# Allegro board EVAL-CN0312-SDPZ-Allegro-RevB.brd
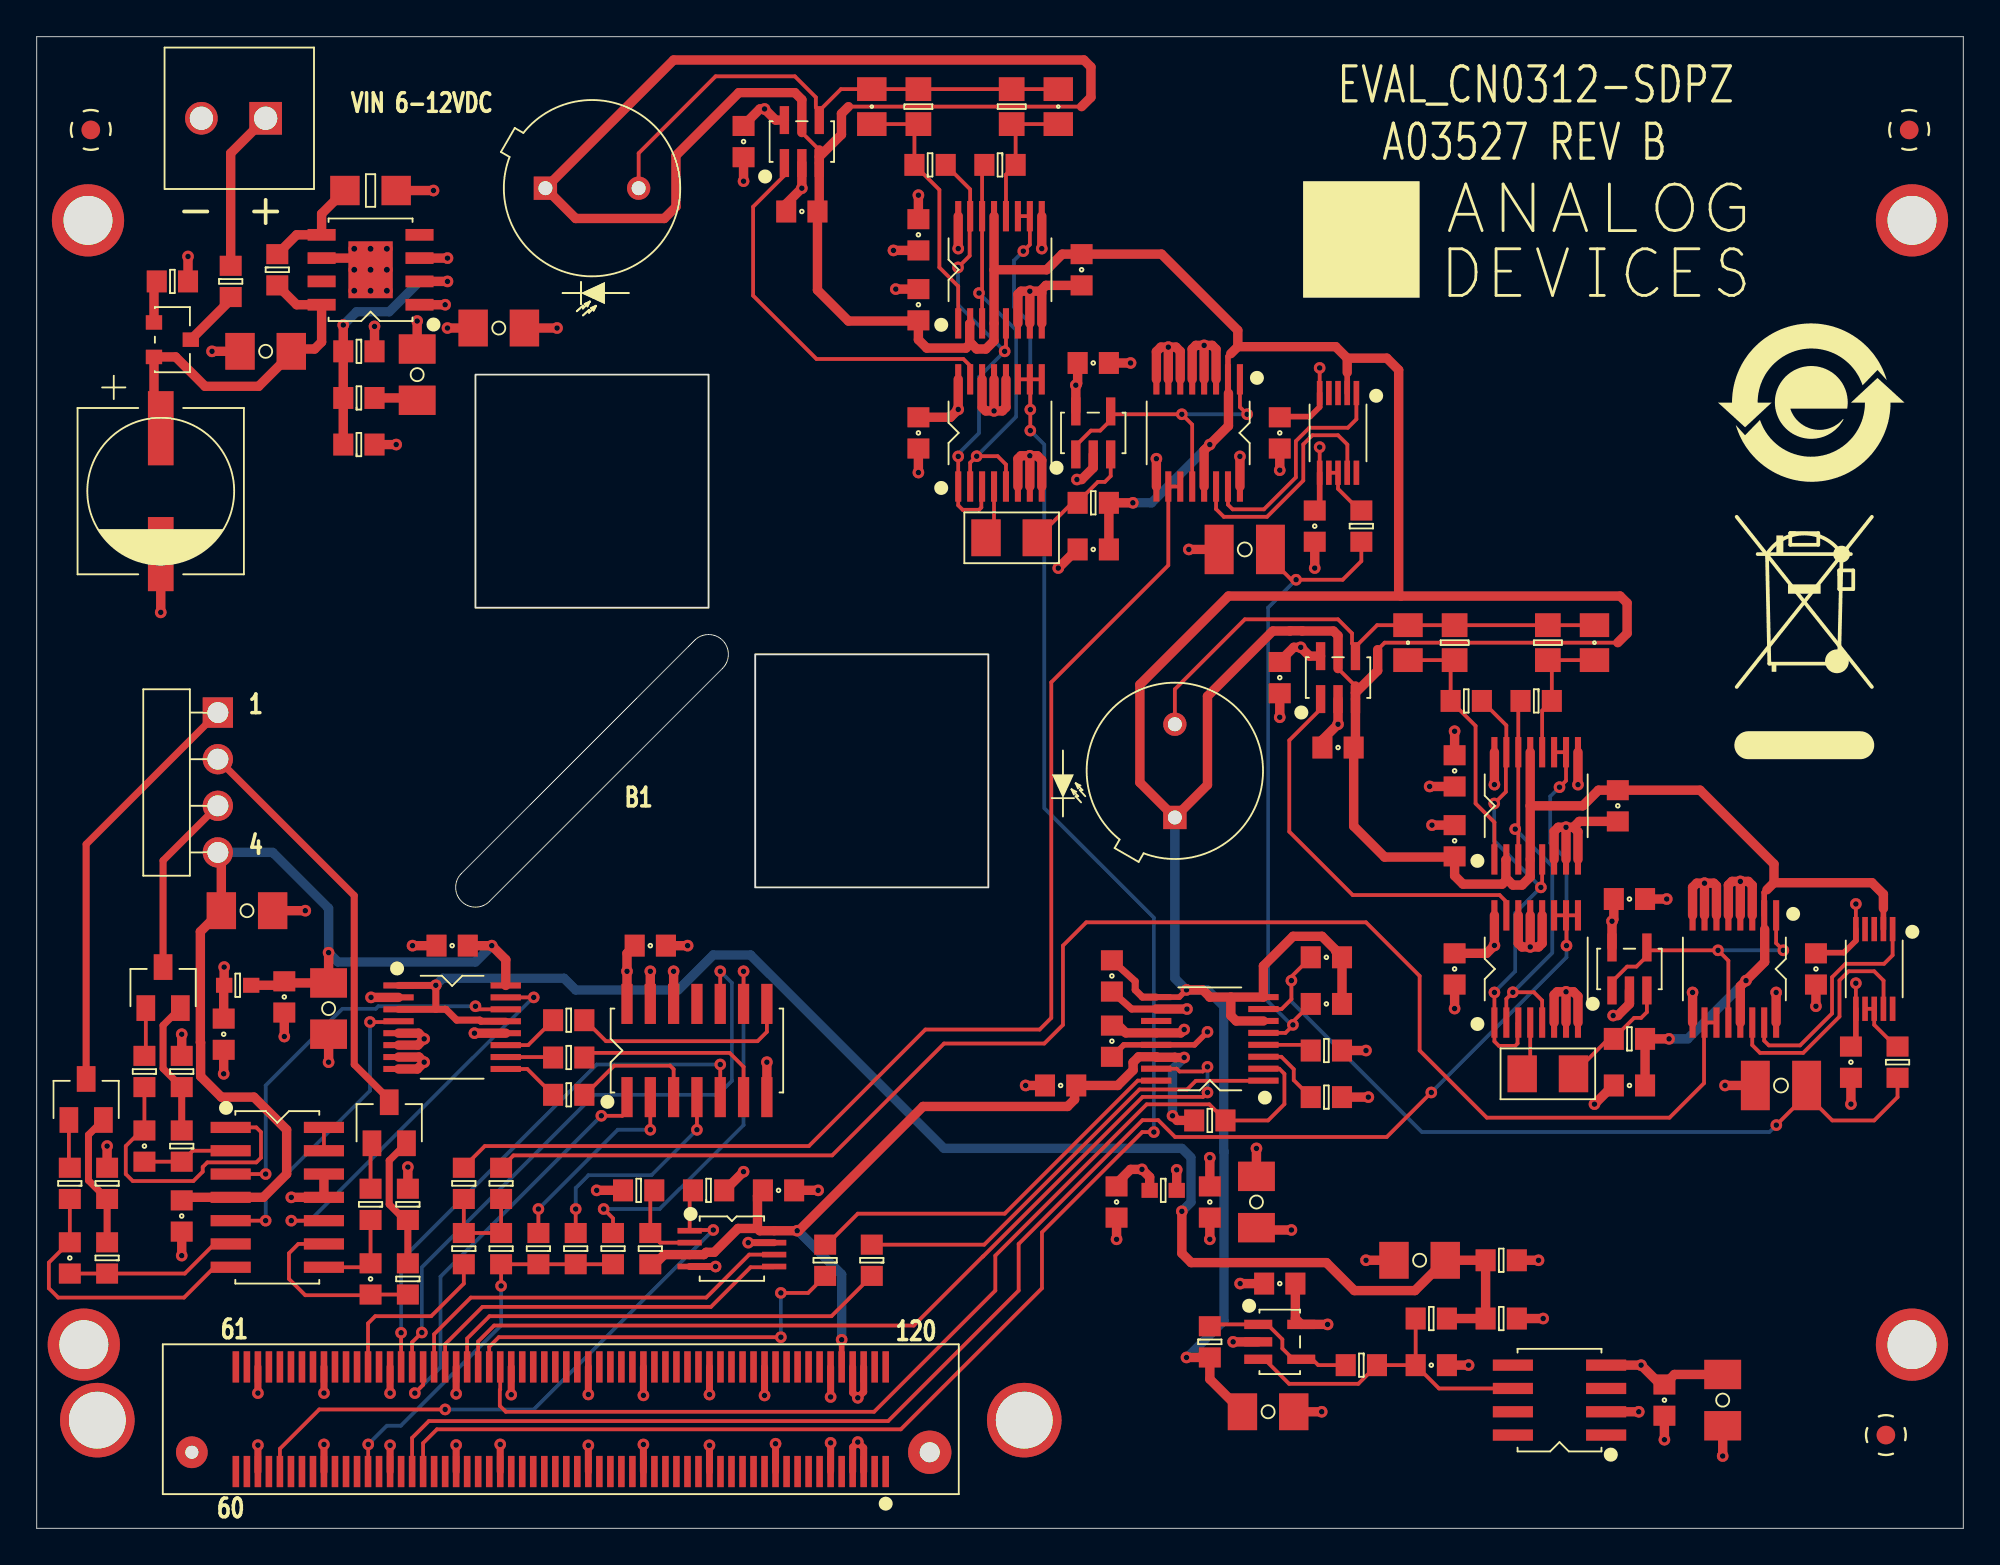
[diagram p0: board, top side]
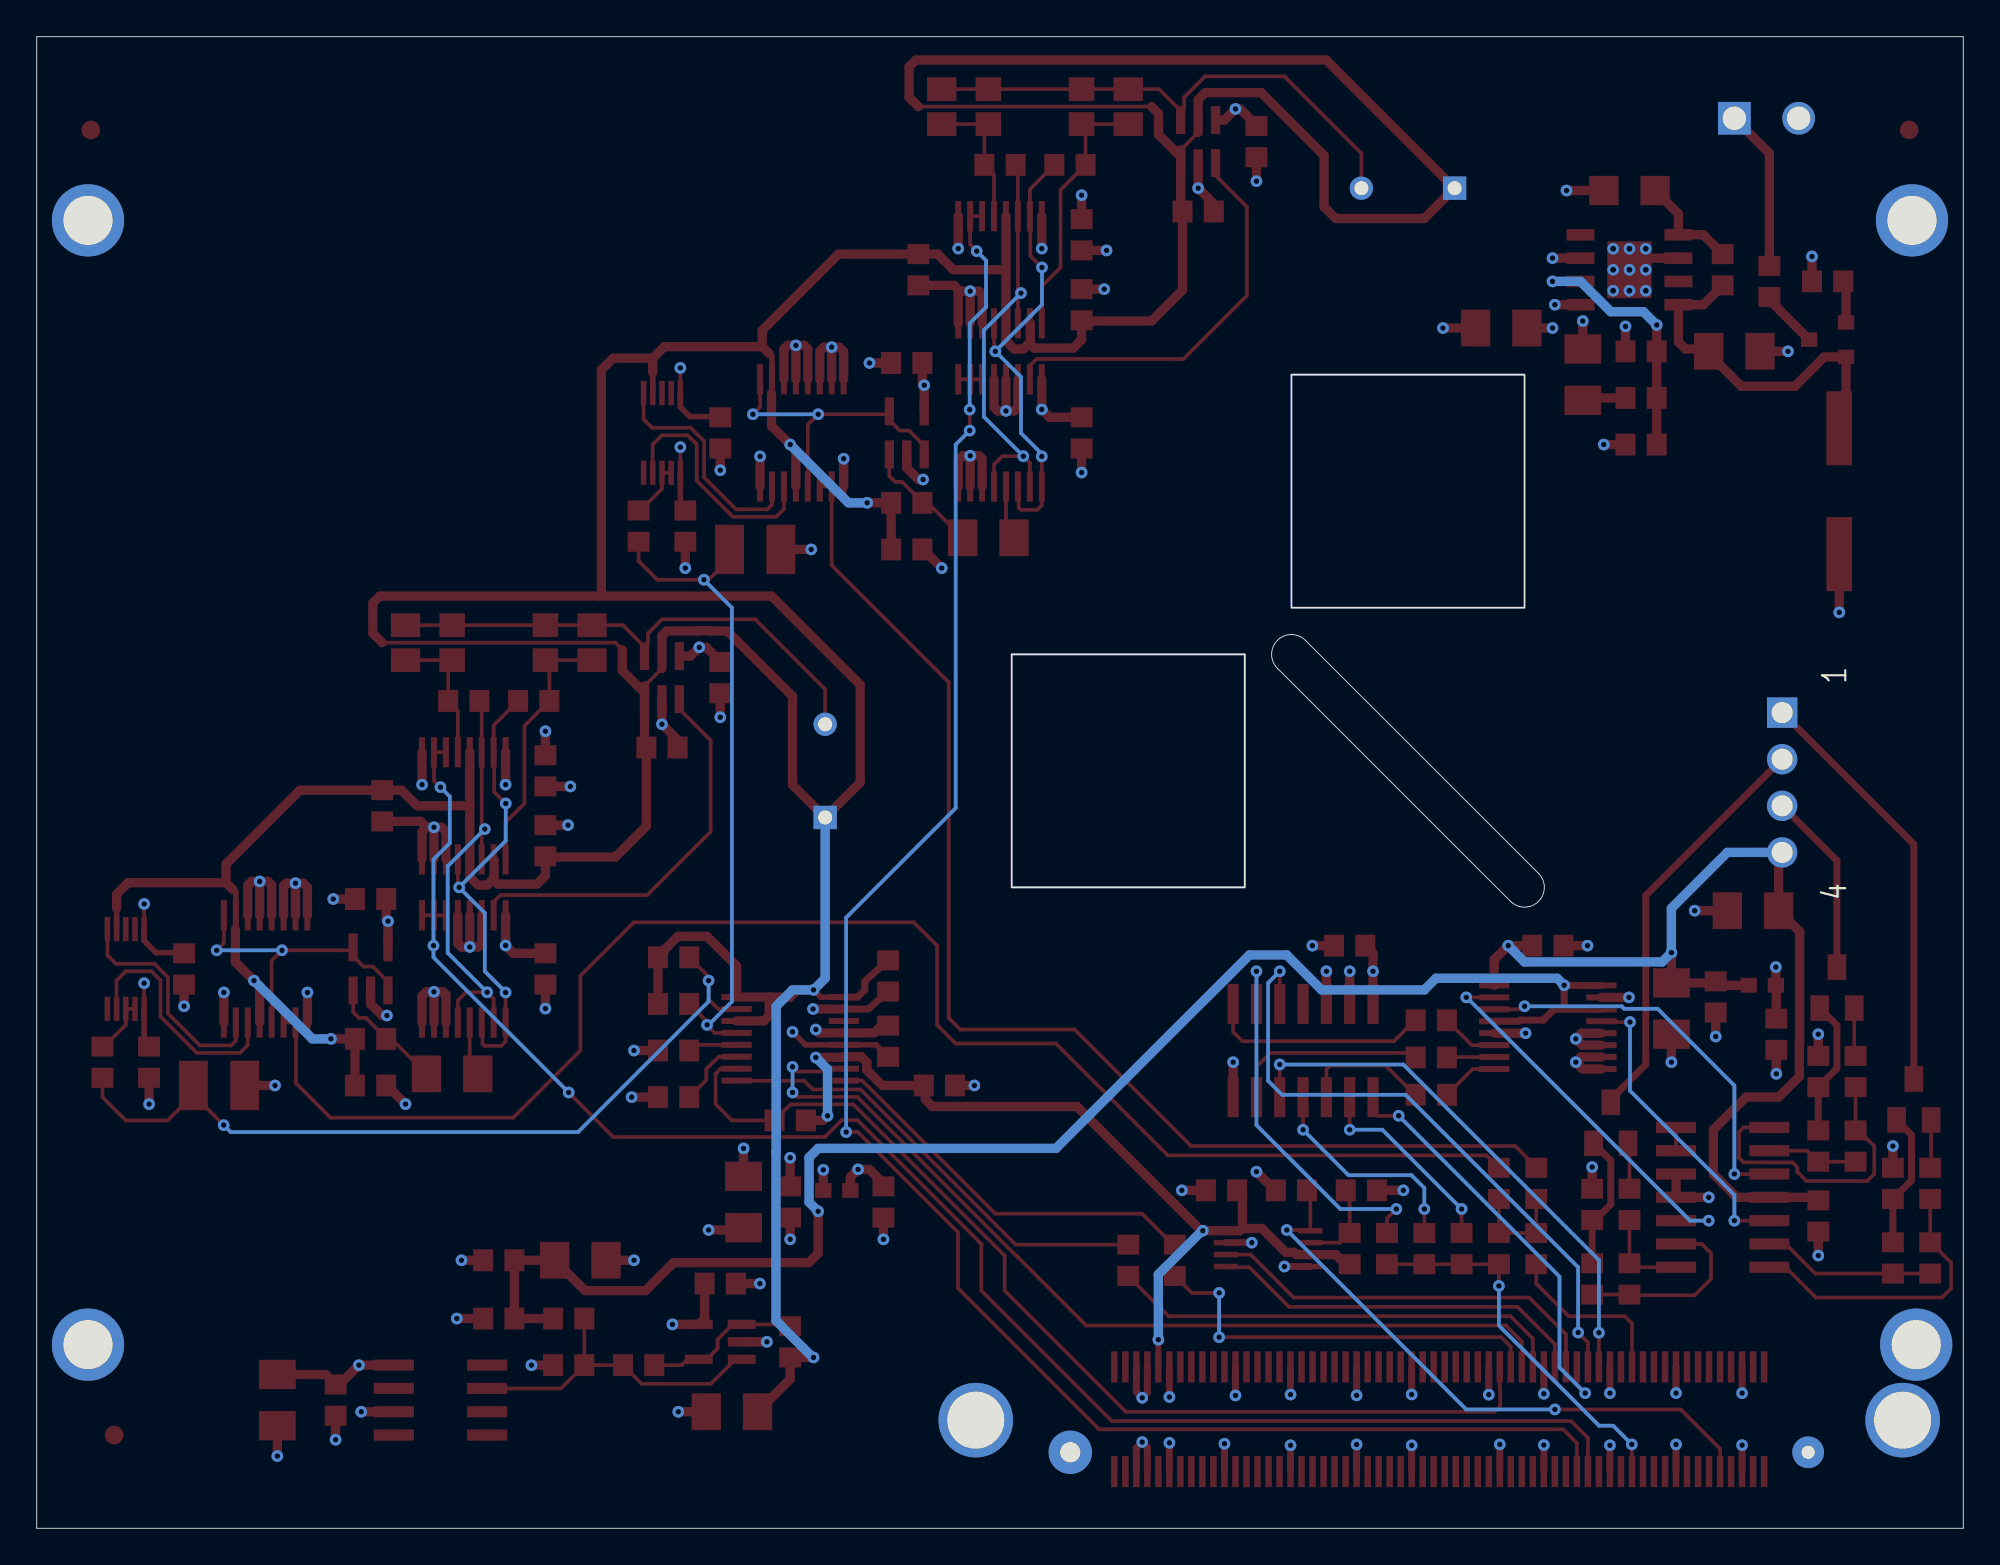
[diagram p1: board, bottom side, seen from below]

Outline 104.95 x 81.28 mm; copper layers: TOP, L2_GND, L3_PWR, BOTTOM. Coordinates in mm from the lower left corner of the outline.
Outline path: rectangle 23.9,50.16 36.6,62.87 ; rectangle 39.14,34.92 51.84,47.62 ; 0,81.28 0,0 104.95,0 104.95,81.28 0,81.28 ; 24.66,34.16 arc(23.14,34.16) 23.14,35.69 35.84,48.39 arc(37.36,48.39) 37.36,46.86 24.66,34.16

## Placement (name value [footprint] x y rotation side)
C1  0.1uF  [C0603]  58.57 30.1 270 top
C2  0.1uF  [C0603]  70.26 28.58 0 top
C3  0.1uF  [C0603]  58.83 17.78 270 top
C4  0.1uF  [C0603]  63.91 17.78 270 top
C5  2.2uF  [C1206]  75.34 14.61 180 top
C6  2.2uF  [C1206]  67.08 6.35 0 top
C7  0.1uF  [C0603]  48.03 66.67 90 top
C8  0.1uF  [C0603]  41.68 71.75 180 top
C9  0.1uF  [C0603]  57.56 53.34 180 top
C10  0.1uF  [C0603]  56.92 68.58 270 top
C11  0.22uF  [C1206H37]  82.32 24.77 0 top
C12  2.2uF  [C1206]  11.46 33.66 0 top
C13  0.1uF  [C0603]  22.63 31.75 180 top
C14  TBD0603  [C0603]  5.87 20.83 90 top
C15  0.1uF  [C0603]  67.72 46.36 270 top
C16  2.2uF  [C1206]  15.9 28.32 270 top
C17  0.1uF  [C0603]  77.24 41.27 270 top
C18  0.1uF  [C0603]  77.24 30.48 270 top
C19  0.1uF  [C0603]  7.9 17.02 270 top
C20  0.1uF  [C0603]  88.67 6.98 90 top
C21  0.1uF  [C0603]  13.49 28.96 270 top
C22  0.1uF  [C0603]  67.72 13.34 180 top
C23  2.2uF  [C1206]  91.85 6.98 90 top
C24  0.22uF  [C1206H37]  53.11 53.98 0 top
C25  2.2uF  [C1206]  66.45 17.78 270 top
C26  4.7pF  [C0805]  45.49 77.47 270 top
C27  0.1uF  [C0603]  38.51 75.56 270 top
C28  0.1uF  [C0603]  55.78 24.13 180 top
C29  15pF  [C0805]  55.65 77.47 270 top
C30  0.1uF  [C0603]  48.03 70.48 270 top
C31  0.1uF  [C0603]  48.03 59.69 270 top
C32  0.1uF  [C0603]  86.77 34.29 0 top
C33  0.1uF  [C0603]  70.89 42.55 180 top
C34  0.1uF  [C0603]  86.77 24.13 180 top
C35  0.1uF  [C0603]  77.24 37.47 90 top
C36  0.1uF  [C0603]  86.13 39.37 270 top
C37  0.1uF  [C0603]  96.93 30.48 90 top
C38  0.1uF  [C0603]  57.56 63.5 0 top
C39  0.1uF  [C0603]  98.83 25.4 270 top
C40  0.1uF  [C0603]  67.72 59.69 90 top
C41  0.1uF  [C0603]  69.62 54.61 270 top
C42  1uF  [C1210]  65.81 53.34 180 top
C43  0.1uF  [C0603]  58.57 26.54 90 top
C44  1uF  [C1210]  95.02 24.13 180 top
C45  0.1uF  [C0603]  75.97 8.89 0 top
C46  0.1uF  [C0603]  70.26 31.12 0 top
C47  0.1uF  [C0603]  40.41 18.41 0 top
C48  TBD0603  [C0603]  1.8 14.73 90 top
C49  0.1uF  [C0603]  33.43 31.75 0 top
C51  100uF  [CPLSML327W327H413]  6.76 56.52 270 top
C52  2.2uF  [C1206]  12.47 64.14 180 top
C53  4.7pF  [C0805]  74.7 48.26 270 top
C54  2.2uF  [C1206]  25.17 65.41 0 top
C55  0.02uF  [C1206]  20.73 62.87 270 top
C56  15pF  [C0805]  84.86 48.26 270 top
C57  0.1uF  [C0603]  10.19 26.92 270 top
C58  TBD0603  [C0603]  18.19 13.59 90 top
D2  S1336-44BK  [TO5_A]  30.25 73.03 0 top
D3  S1336-44BK  [TO5_A]  62 41.27 90 top
J1  TSW-104-09-G-S-RA  [CNSAMTECTSW-104-09-G-S-RA]  6.76 40.64 270 top
J2  25.195.0253.0  [CNWIELAND0253]  12.47 76.84 180 top
J4  FX8-120S-SV(21)  [CNHRSFX8-120S-SV]  28.55 5.94 180 top
L1  330OHM  [L0603]  61.37 18.41 180 top
L2  330OHM  [L0603]  10.95 29.59 180 top
NOREF  -  []  104.95 0 90 top
NOREF#2  -  [unnamed#2]  102.16 71.27 0 top
NOREF#3  -  []  161.7 251.46 0 top
NOREF#4  -  []  0 81.28 0 top
NOREF#5  -  []  96.67 61.34 0 top
NOREF#6  -  [unnamed#2]  2.95 76.2 0 top
NOREF#7  -  []  30.25 67.31 180 top
NOREF#8  -  []  3.3 4.62 0 top
NOREF#9  -  []  39.14 46.36 0 top
NOREF#10  -  []  0 81.28 270 top
NOREF#11  -  []  3.3 5.89 0 top
NOREF#12  -  []  30.25 67.31 180 top
NOREF#13  -  [unnamed#2]  102.01 76.2 0 top
NOREF#14  -  []  -191.36 -58.42 0 top
NOREF#15  -  []  23.9 34.92 90 top
NOREF#16  -  []  53.8 5.89 90 top
NOREF#17  -  []  52.53 5.89 90 top
NOREF#18  -  [unnamed#2]  53.8 5.89 0 top
NOREF#19  -  []  0 0 0 top
NOREF#20  -  []  -115.16 -124.46 0 top
NOREF#21  -  [unnamed#2]  3.3 5.89 0 top
NOREF#22  -  []  55.91 40.39 270 top
NOREF#23  -  []  190.91 -1.27 0 top
NOREF#24  -  []  -256.77 -241.94 0 top
NOREF#25  -  [unnamed#2]  100.74 5.08 0 top
NOREF#26  -  []  0 0 90 top
NOREF#27  -  []  105.56 58.8 0 top
NOREF#28  -  []  -214.22 213.36 0 top
NOREF#29  -  []  0 0 0 top
NOREF#30  -  []  0 0 0 top
NOREF#31  -  []  35.33 50.16 90 top
NOREF#32  -  []  104.95 81.28 180 top
NOREF#33  -  []  23.42 33.96 0 top
NOREF#34  -  []  23.9 34.92 0 top
NOREF#35  -  []  0 0 90 top
NOREF#36  -  [unnamed#2]  2.79 71.27 0 top
NOREF#37  -  [unnamed#2]  2.57 10.01 0 top
NOREF#38  -  []  104.95 0 90 top
NOREF#39  -  [unnamed#2]  102.16 10.01 0 top
NOREF#40  -  []  54.38 93.98 0 top
NOREF#41  -  []  68.99 67.06 180 bottom
Q1  MMBT4401  [SOT23]  6.88 29.46 0 top
Q2  MMBT4401  [SOT23]  2.69 23.37 0 top
Q3  MMBT4401  [SOT23]  19.2 22.1 0 top
Q4  SI2301CDS-T1-E3  [SOT23-M3]  7.39 64.77 270 top
R1  10K  [R0603]  57.56 55.88 0 top
R2  1MEG  [R0805]  48.03 77.47 270 top
R3  33  [R0603]  5.87 24.89 90 top
R4  10K  [R0603]  75.97 11.43 0 top
R5  10K  [R0603]  79.78 11.43 0 top
R6  TBD0603  [R0603]  52.48 74.3 180 top
R7  TBD0603  [R0603]  48.67 74.3 0 top
R8  10K  [R0603]  86.77 26.67 0 top
R9  10K  [R0603]  72.16 54.61 270 top
R10  10K  [R0603]  101.37 25.4 270 top
R11  TBD0603  [R0603]  77.88 45.09 0 top
R12  100  [R0603]  7.9 24.89 90 top
R13  33  [R0603]  7.9 20.83 90 top
R14  1MEG  [R0805]  77.24 48.26 270 top
R15  0  [R0603]  72.16 8.89 180 top
R16  10K  [R0603]  70.26 26.04 0 top
R17  10K  [R0603]  70.26 23.5 0 top
R18  100  [R0603]  3.84 18.8 90 top
R19  33  [R0603]  1.8 18.8 90 top
R20  10K  [R0603]  79.78 14.61 0 top
R21  33K  [R0805]  53.11 77.47 270 top
R22  0  [R0603]  45.49 14.61 90 top
R23  0  [R0603]  42.95 14.61 90 top
R24  33  [R0603]  3.84 14.73 90 top
R25  100  [R0603]  20.22 17.65 90 top
R26  33  [R0603]  18.19 17.65 90 top
R27  TBD0603  [R0603]  81.69 45.09 180 top
R28  0  [R0603]  63.91 10.16 270 top
R29  0  [R0603]  27.33 15.24 90 top
R30  33  [R0603]  20.22 13.59 90 top
R31  TBD0603  [R0603]  33.43 15.24 90 top
R32  100K  [R0603]  36.6 18.41 0 top
R33  100K  [R0603]  63.91 22.23 180 top
R34  0  [R0603]  23.27 15.24 90 top
R35  0  [R0603]  29.36 15.24 90 top
R36  0  [R0603]  25.3 15.24 90 top
R37  0  [R0603]  31.39 15.24 90 top
R38  100  [R0603]  7.39 67.94 0 top
R39  0  [R0603]  23.27 18.8 90 top
R40  0  [R0603]  25.3 18.8 90 top
R41  0  [R0603]  28.98 23.62 180 top
R42  0  [R0603]  28.98 25.65 180 top
R43  0  [R0603]  28.98 27.69 180 top
R44  0  [R0603]  10.57 67.94 270 top
R46  100K  [R0603]  32.79 18.41 180 top
R48  100K  [R0603]  13.11 68.58 270 top
R49  28K  [R1206]  18.19 72.9 0 top
R50  47K  [R0603]  17.55 59.05 0 top
R51  47K  [R0603]  17.55 61.59 0 top
R52  154K  [R0603]  17.55 64.14 180 top
R54  33K  [R0805]  82.32 48.26 270 top
U1  ADG633YRUZ  [TSSOP16]  81.69 30.48 0 top
U2  ADG633YRUZ  [TSSOP16]  81.69 39.37 0 top
U3  AD8615AUJZ  [TSOT-5]  86.77 30.48 0 top
U4  ADG633YRUZ  [TSSOP16]  22.63 27.3 270 top
U5  AD8615AUJZ  [TSOT-5]  70.89 46.36 0 top
U6  AD8618ARZ  [SO14]  13.11 18.03 270 top
U7  AD8615AUJZ  [TSOT-5]  41.68 75.56 0 top
U8  24LC32A-I/MS  [MSOP8]  37.87 15.24 270 top
U9  ADG633YRUZ  [TSSOP16]  52.48 59.69 0 top
U10  ADG633YRUZ  [TSSOP16]  52.48 68.58 0 top
U11  ADG733BRUZ  [TSSOP16]  92.48 30.48 180 top
U12  AD8271ARMZ  [RM10]  100.1 30.48 180 top
U13  AD7798BRUZ  [TSSOP16]  63.91 26.67 90 top
U14  AD8615AUJZ  [TSOT-5]  57.56 59.69 0 top
U15  74AHCT08D,118  [SO14]  35.97 26.04 0 top
U16  ADG733BRUZ  [TSSOP16]  63.27 59.69 180 top
U17  AD8271ARMZ  [RM10]  70.89 59.69 180 top
U18  ADR4525BRZ  [SO8]  82.96 6.98 90 top
U19  AD8605ARTZ  [SOT23-5L]  67.72 10.16 270 top
U20  ADP7104ARDZ  [SO8NB-PAD3_1X2_41]  18.19 68.58 90 top

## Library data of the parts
C1-C4 C7-C10 C13 C15 C17-C22 C27 C28 C30-C41 C43 C45-C47 C49 C57 = CAP: Tolerance: 10; User Part Number: UPN; alternate symbols: (C0402H22_ALT,C0201-2); part number: CAP_SM-0.1UF,100V,10,E013624,C0603; tolerance: 10
C5 C6 C12 C16 C23 C25 C52 C54 = CAP: Tolerance: 10; User Part Number: UPN; alternate symbols: (C0402H22_ALT,C0201-2); part number: CAP_SM-2.2UF,16V,10,E012605,C1206; tolerance: 10
C11 C24 = CAP: Tolerance: 20; User Part Number: UPN; alternate symbols: (C0402H22_ALT,C0201-2); part number: CAP_SM-0.22UF,16V,20,E016730,C1206H37; tolerance: 20
C14 C48 C58 = CAP: User Part Number: UPN; alternate symbols: (C0402H22_ALT,C0201-2); part number: CAP_SM-TBD0603,TBD0603,TBD0603,E000382,C0603
C26 C53 = CAP: Tolerance: 0.25pF; User Part Number: UPN; alternate symbols: (C0402H22_ALT,C0201-2); part number: CAP_SM-4.7PF,50V,0.25PF,E014250,C0805; tolerance: 0.25pF
C29 C56 = CAP: Tolerance: 5; User Part Number: UPN; alternate symbols: (C0402H22_ALT,C0201-2); part number: CAP_SM-15PF,50V,5,E012708,C0805; tolerance: 5
C42 C44 = CAP: Tolerance: 10; User Part Number: UPN; alternate symbols: (C0402H22_ALT,C0201-2); part number: CAP_SM-1UF,50V,10,E011765,C1210; tolerance: 10
C51 = CAPP: Tolerance: 20; User Part Number: UPN; part number: CAPP_SM-100UF,25V,20,E016686,CPLSML327W327H413; tolerance: 20
C55 = CAP: Tolerance: 5; User Part Number: UPN; alternate symbols: (C0402H22_ALT,C0201-2); part number: CAP_SM-0.02UF,50V,5,E013532,C1206; tolerance: 5
D2 D3 = DIOPHOTO_V2: User Part Number: UPN; Tolerance: N/A; part number: DIOPHOTO_V2_TH-S1336-44BK,5V,N/A,E018050,TO5_A; tolerance: N/A
J1 = CN4P: User Part Number: UPN; part number: CN4P_TH-TSW-104-09-G-S-RA,E007556,CNSAMTECTSW-104-09-G-S-RA
J2 = CN2P: User Part Number: UPN; part number: CN2P_TH-25.195.0253.0,E016527,CNWIELAND0253
J4 = CN120P_V2: User Part Number: UPN; part number: CN120P_V2_SM-FX8-120S-SV(21),E010527,CNHRSFX8-120S-SV
L1 L2 = FERRITE: Tolerance: 25; User Part Number: UPN; part number: FERRITE_SM-330OHM,25,E016683,L0603; tolerance: 25
Q1-Q3 = TRANMMBT4401: User Part Number: UPN; part number: TRANMMBT4401_SM-MMBT4401,E004667,SOT23
Q4 = TRANSI2301DS: User Part Number: UPN; part number: TRANSI2301DS_SM-SI2301CDS-T1-E3,E016690,SOT23-M3
R1 R4 R5 R8-R10 R16 R17 R20 = RES: Tolerance: 1; User Part Number: UPN; alternate symbols: (RRAD984L1500W75H520LD32); part number: RES_SM-10K,1/16W,1,E007899,R0603; tolerance: 1
R2 R14 = RES: Tolerance: 1; User Part Number: UPN; alternate symbols: (RRAD984L1500W75H520LD32); part number: RES_SM-1MEG,1/8W,1,E003518,R0805; tolerance: 1
R3 R13 R19 R24 R26 R30 = RES: Tolerance: 1; User Part Number: UPN; alternate symbols: (RRAD984L1500W75H520LD32); part number: RES_SM-33,1/16W,1,E004232,R0603; tolerance: 1
R6 R7 R11 R27 R31 = RES: User Part Number: UPN; alternate symbols: (RRAD984L1500W75H520LD32); part number: RES_SM-TBD0603,TBD0603,TBD0603,E004050,R0603
R12 R18 R25 R38 = RES: Tolerance: 0.1; User Part Number: UPN; alternate symbols: (RRAD984L1500W75H520LD32); part number: RES_SM-100,1/10W,0.1,E003963,R0603; tolerance: 0.1
R15 R22 R23 R28 R29 R34-R37 R39-R44 = RES: Tolerance: 1; User Part Number: UPN; alternate symbols: (RRAD984L1500W75H520LD32); part number: RES_SM-0,1/16W,1,E004207,R0603; tolerance: 1
R21 R54 = RES: Tolerance: 1; User Part Number: UPN; alternate symbols: (RRAD984L1500W75H520LD32); part number: RES_SM-33K,1/10W,1,E004180,R0805; tolerance: 1
R32 R33 R46 R48 = RES: Tolerance: 0.5; User Part Number: UPN; alternate symbols: (RRAD984L1500W75H520LD32); part number: RES_SM-100K,1/10W,0.5,E012705,R0603; tolerance: 0.5
R49 = RES: Tolerance: 1; User Part Number: UPN; alternate symbols: (RRAD984L1500W75H520LD32); part number: RES_SM-28K,1/4W,1,E003411,R1206; tolerance: 1
R50 R51 = RES: Tolerance: 1; User Part Number: UPN; alternate symbols: (RRAD984L1500W75H520LD32); part number: RES_SM-47K,1/16W,1,E004240,R0603; tolerance: 1
R52 = RES: Tolerance: 1; User Part Number: UPN; alternate symbols: (RRAD984L1500W75H520LD32); part number: RES_SM-154K,1/10W,1,E013894,R0603; tolerance: 1
U1 U2 U4 U9 U10 = ADG733: User Part Number: UPN; part number: ADG733_SM-ADG633YRUZ,E012053,TSSOP16,N/A
U3 U5 U7 U14 = AD8605: User Part Number: UPN; part number: AD8605_SM-AD8615AUJZ,E016677,TSOT-5,N/A
U6 = AD713N: User Part Number: UPN; part number: AD713N_SM-AD8618ARZ,E016678,SO14,N/A
U8 = IC24FC256: User Part Number: UPN; part number: IC24FC256_SM-24LC32A-I/MS,E014160,MSOP8
U11 U16 = ADG733: User Part Number: UPN; part number: ADG733_SM-ADG733BRUZ,E011902,TSSOP16,N/A
U12 U17 = AD8271: User Part Number: UPN; part number: AD8271_SM-AD8271ARMZ,E016676,RM10,N/A
U13 = AD779X: User Part Number: UPN; part number: AD779X_SM-AD7798BRUZ,E014198,TSSOP16,N/A
U15 = 7408: User Part Number: UPN; part number: 7408_SM-74AHCT08D,118,E016681,SO14
U18 = ADR45XX: User Part Number: UPN; part number: ADR45XX_SM-ADR4525BRZ,E016680,SO8,N/A
U19 = AD8605: User Part Number: UPN; part number: AD8605_SM-AD8605ARTZ,E006651,SOT23-5L,AD8605
U20 = ADP7104: User Part Number: UPN; part number: ADP7104_SM-ADP7104ARDZ,E016787,SO8NB-PAD3_1X2_41,N/A

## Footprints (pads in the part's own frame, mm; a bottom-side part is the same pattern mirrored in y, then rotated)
C0603
  rect 1.092x1.194 smd: 1(-0.851,0) 2(0.851,0)
C0805
  rect 1.295x1.6 smd: 1(-0.953,0) 2(0.953,0)
C1206
  rect 1.6x2.007 smd: 1(-1.397,0) 2(1.397,0)
C1206H37
  rect 1.6x2.007 smd: 1(-1.397,0) 2(1.397,0)
C1210
  rect 1.575x2.692 smd: 1(-1.397,0) 2(1.397,0)
CNHRSFX8-120S-SV
  round 2.362 hole 1.092 unplated: (-20.099,1.801)
  round 1.727 hole 0.711 unplated: (20.099,1.801)
  rect 0.356x1.702 smd: 1(-17.701,2.85) 2(-17.099,2.85) 3(-16.5,2.85) 4(-15.9,2.85) 5(-15.301,2.85) 6(-14.699,2.85) 7(-14.1,2.85) 8(-13.5,2.85) 9(-12.901,2.85) 10(-12.301,2.85) 11(-11.699,2.85) 12(-11.1,2.85) 13(-10.5,2.85) 14(-9.901,2.85) 15(-9.299,2.85) 16(-8.7,2.85) 17(-8.1,2.85) 18(-7.501,2.85) 19(-6.901,2.85) 20(-6.299,2.85) 21(-5.7,2.85) 22(-5.1,2.85) 23(-4.501,2.85) 24(-3.899,2.85) 25(-3.299,2.85) 26(-2.7,2.85) 27(-2.101,2.85) 28(-1.501,2.85) 29(-0.899,2.85) 30(-0.3,2.85) 31(0.3,2.85) 32(0.899,2.85) 33(1.501,2.85) 34(2.101,2.85) 35(2.7,2.85) 36(3.299,2.85) 37(3.899,2.85) 38(4.501,2.85) 39(5.1,2.85) 40(5.7,2.85) 41(6.299,2.85) 42(6.901,2.85) 43(7.501,2.85) 44(8.1,2.85) 45(8.7,2.85) 46(9.299,2.85) 47(9.901,2.85) 48(10.5,2.85) 49(11.1,2.85) 50(11.699,2.85) 51(12.301,2.85) 52(12.901,2.85) 53(13.5,2.85) 54(14.1,2.85) 55(14.699,2.85) 56(15.301,2.85) 57(15.9,2.85) 58(16.5,2.85) 59(17.099,2.85) 60(17.701,2.85) 61(17.701,-2.85) 62(17.099,-2.85) 63(16.5,-2.85) 64(15.9,-2.85) 65(15.301,-2.85) 66(14.699,-2.85) 67(14.1,-2.85) 68(13.5,-2.85) 69(12.901,-2.85) 70(12.301,-2.85) 71(11.699,-2.85) 72(11.1,-2.85) 73(10.5,-2.85) 74(9.901,-2.85) 75(9.299,-2.85) 76(8.7,-2.85) 77(8.1,-2.85) 78(7.501,-2.85) 79(6.901,-2.85) 80(6.299,-2.85) 81(5.7,-2.85) 82(5.1,-2.85) 83(4.501,-2.85) 84(3.899,-2.85) 85(3.299,-2.85) 86(2.7,-2.85) 87(2.101,-2.85) 88(1.501,-2.85) 89(0.899,-2.85) 90(0.3,-2.85) 91(-0.3,-2.85) 92(-0.899,-2.85) 93(-1.501,-2.85) 94(-2.101,-2.85) 95(-2.7,-2.85) 96(-3.299,-2.85) 97(-3.899,-2.85) 98(-4.501,-2.85) 99(-5.1,-2.85) 100(-5.7,-2.85) 101(-6.299,-2.85) 102(-6.901,-2.85) 103(-7.501,-2.85) 104(-8.1,-2.85) 105(-8.7,-2.85) 106(-9.299,-2.85) 107(-9.901,-2.85) 108(-10.5,-2.85) 109(-11.1,-2.85) 110(-11.699,-2.85) 111(-12.301,-2.85) 112(-12.901,-2.85) 113(-13.5,-2.85) 114(-14.1,-2.85) 115(-14.699,-2.85) 116(-15.301,-2.85) 117(-15.9,-2.85) 118(-16.5,-2.85) 119(-17.099,-2.85) 120(-17.701,-2.85)
CNSAMTECTSW-104-09-G-S-RA
  rect 1.651x1.651 hole 1.143: 1(-3.81,3.111)
  round 1.651 hole 1.143: 2(-1.27,3.111) 3(1.27,3.111) 4(3.81,3.111)
CNWIELAND0253
  rect 1.778x1.778 hole 1.27: 1(0,0)
  round 1.778 hole 1.27: 2(3.5,0)
CPLSML327W327H413
  rect 4.039x1.397 smd: N(3.429,0) P(-3.429,0)
L0603
  rect 0.889x0.813 smd: 1(-0.737,0) 2(0.737,0)
MSOP8
  rect 0.305x1.321 smd: 1(-0.975,-2.301) 2(-0.325,-2.301) 3(0.325,-2.301) 4(0.975,-2.301) 5(0.975,2.301) 6(0.325,2.301) 7(-0.325,2.301) 8(-0.975,2.301)
R0603
  rect 1.092x1.194 smd: 1(-0.851,0) 2(0.851,0)
R0805
  rect 1.295x1.397 smd: 1(-0.953,0) 2(0.953,0)
R1206
  rect 1.6x1.6 smd: 1(-1.397,0) 2(1.397,0)
RM10
  rect 0.305x1.321 smd: 1(-1.001,-2.172) 2(-0.5,-2.172) 3(0,-2.172) 4(0.5,-2.172) 5(1.001,-2.172) 6(1.001,2.172) 7(0.5,2.172) 8(0,2.172) 9(-0.5,2.172) 10(-1.001,2.172)
SO8
  rect 0.61x2.184 smd: 1(-1.905,-2.54) 2(-0.635,-2.54) 3(0.635,-2.54) 4(1.905,-2.54) 5(1.905,2.54) 6(0.635,2.54) 7(-0.635,2.54) 8(-1.905,2.54)
SO8NB-PAD3_1X2_41
  rect 0.635x1.524 smd: 1(-1.905,-2.667) 2(-0.635,-2.667) 3(0.635,-2.667) 4(1.905,-2.667) 5(1.905,2.667) 6(0.635,2.667) 7(-0.635,2.667) 8(-1.905,2.667)
  rect 3.099x2.413 smd: PAD(0,0)
SO14
  rect 0.61x2.184 smd: 1(-3.81,-2.54) 2(-2.54,-2.54) 3(-1.27,-2.54) 4(0,-2.54) 5(1.27,-2.54) 6(2.54,-2.54) 7(3.81,-2.54) 8(3.81,2.54) 9(2.54,2.54) 10(1.27,2.54) 11(0,2.54) 12(-1.27,2.54) 13(-2.54,2.54) 14(-3.81,2.54)
SOT23
  rect 1.016x1.397 smd: 1(-0.94,-1.118) 2(0.94,-1.118) 3(0,1.118)
SOT23-5L
  rect 0.508x1.524 smd: 1(-0.95,-1.171) 2(0,-1.171) 3(0.95,-1.171) 4(0.95,1.171) 5(-0.95,1.171)
SOT23-M3
  rect 0.787x0.889 smd: 1(-0.94,-1.003) 2(0.94,-1.003) 3(0,1.003)
TO5_A
  rect 1.27x1.27 hole 0.762: 1(-2.54,0)
  round 1.27 hole 0.762: 2(2.54,0)
TSOT-5
  rect 0.508x1.524 smd: 1(-0.95,-1.171) 2(0,-1.171) 3(0.95,-1.171) 4(0.95,1.171) 5(-0.95,1.171)
TSSOP16
  rect 0.33x1.651 smd: 1(-2.276,-2.921) 2(-1.626,-2.921) 3(-0.975,-2.921) 4(-0.325,-2.921) 5(0.325,-2.921) 6(0.975,-2.921) 7(1.626,-2.921) 8(2.276,-2.921) 9(2.276,2.921) 10(1.626,2.921) 11(0.975,2.921) 12(0.325,2.921) 13(-0.325,2.921) 14(-0.975,2.921) 15(-1.626,2.921) 16(-2.276,2.921)
unnamed#2
  round 3.937 hole 2.667 unplated: (0,0)

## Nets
0.83VREF: C5.1(N1) R4.2(N2) R5.1(N1) R20.1(N1) U4.1(S2B) U4.3(S3B) U4.13(S1B)
+3.3V: C28.1(N1) C47.1(N1) J4.116(N5) R31.1(N1) R33.2(N2) U8.3(A2) U8.8(VCC) U13.14(DVDD)
AGND: C1.2(N2) C3.2(N2) C4.2(N2) C5.2(N2) C6.2(N2) C7.2(N2) C8.2(N2) C9.2(N2) C10.2(N2) C12.2(N2) C13.2(N2) C15.2(N2) C16.2(N2) C17.2(N2) C18.2(N2) C19.2(N2) C20.2(N2) C21.2(N2) C22.2(N2) C23.2(N2) C25.2(N2) C27.2(N2) C28.2(N2) C30.2(N2) C31.2(N2) C32.2(N2) C33.2(N2) C34.2(N2) C35.2(N2) C36.2(N2) C37.2(N2) C38.2(N2) C39.2(N2) C40.2(N2) C41.2(N2) C42.2(N2) C43.2(N2) C44.2(N2) C45.2(N2) C47.2(N2) C49.2(N2) C51.N(N2) C52.2(N2) C54.2(N2) C57.2(N2) J2.2(N2) J4.3(N3) J4.4(N4) J4.6(N6) J4.11(N11) J4.17(N17) J4.23(N23) J4.28(N28) J4.36(N36) J4.40(N40) J4.46(N46) J4.52(N52) J4.58(N58) J4.63(N58) J4.69(N52) J4.75(N46) J4.81(N40) J4.86(N35) J4.93(N28) J4.98(N23) J4.104(N17) J4.109(N12) J4.115(N6) J4.117(N4) J4.118(N3) R5.2(N2) R12.2(N2) R16.2(N2) R17.2(N2) R18.2(N2) R20.2(N2) R25.2(N2) R32.2(N2) R38.2(N2) R46.2(N2) R49.2(N2) R50.2(N2) U1.6(EN_N) U1.7(VSS) U1.8(GND) U1.12(S1A) U1.13(S1B) U1.14(D1) U2.6(EN_N) U2.7(VSS) U2.8(GND) U2.9(A2) U3.2(V-) U4.2(S2A) U4.5(S3A) U4.6(EN_N) U4.7(VSS) U4.8(GND) U4.12(S1A) U5.2(V-) U6.11(V-) U6.12(NINV) U7.2(V-) U8.4(VSS) U8.7(WP) U9.6(EN_N) U9.7(VSS) U9.8(GND) U9.12(S1A) U9.13(S1B) U9.14(D1) U10.6(EN_N) U10.7(VSS) U10.8(GND) U10.9(A2) U11.3(S3B) U11.4(D3) U11.5(S3A) U11.6(EN_N) U11.7(VSS) U11.8(GND) U11.9(A2) U12.5(-VS) U13.10(REFIN_NEG) U13.12(GND) U14.2(V-) U15.7(GND) U15.12(A) U15.13(B) U16.3(S3B) U16.4(D3) U16.5(S3A) U16.6(EN_N) U16.7(VSS) U16.8(GND) U16.9(A2) U17.5(-VS) U18.4(GND) U19.2(V-) U20.3(GND1) U20.6(GND2) U20.PAD
AVCC: C4.1(N1) C15.1(N1) C17.1(N1) C18.1(N1) C20.1(N1) C22.1(N1) C23.1(N1) C25.1(N1) C27.1(N1) C30.1(N1) C31.1(N1) C32.1(N1) C37.1(N1) C38.1(N1) C39.1(N1) C40.1(N1) C41.1(N1) C43.1(N1) L1.1(N1) U1.16(VDD) U2.16(VDD) U3.5(V+) U5.5(V+) U7.5(V+) U9.16(VDD) U10.16(VDD) U11.16(VDD) U12.6(+VS) U13.13(AVDD) U14.5(V+) U16.16(VDD) U17.6(+VS) U18.2(VIN) U19.5(V+)
DVCC: C3.1(N1) C49.1(N1) C54.1(N1) C55.1(N1) C57.1(N1) L1.2(N2) L2.2(N2) R52.1(N1) U15.14(VCC) U20.1(VOUT)
CHAN0_GO/G1: J4.43(N43) U9.9(A2) U9.10(A1) U9.11(A0) U10.10(A1) U10.11(A0)
CHAN1_GO/G1: J4.44(N44) U1.9(A2) U1.10(A1) U1.11(A0) U2.10(A1) U2.11(A0)
LED_BLUE: J1.3(N3) Q1.3(C)
LED_BLUE_ON: J4.77(N44) U15.10(B)
LED_CLK: J4.48(N48) R29.1(N1) R35.1(N1) R36.1(N1) R37.1(N1)
LED_CLK_BLUE: R43.2(N2) U4.11(A0)
LED_CLK_GREEN: R42.2(N2) U4.10(A1)
LED_CLK_RED: R41.2(N2) U4.9(A2)
LED_GREEN: J1.2(N2) Q3.3(C)
LED_GREEN_ON: J4.76(N45) U15.5(B)
LED_RED: J1.1(N1) Q2.3(C)
LED_RED_ON: J4.78(N43) U15.1(A)
LED_VCC: C12.1(N1) C13.1(N1) C16.1(N1) C19.1(N1) C21.1(N1) J1.4(N4) L2.1(N1) U4.16(VDD) U6.4(V+)
SPI_CLK: R22.2(N2) U13.1(SCLK)
SPI_MISO: J4.83(N38) U13.15(DOUT_RDY_N)
SPI_MOSI: R23.2(N2) U13.16(DIN)
SPI_SEL_A: J4.85(N36) R33.1(N1) U13.2(CS_N)
SYNCH_CLK_0: R39.2(N2) U16.10(A1) U16.11(A0)
SYNCH_CLK_1: R40.2(N2) U11.10(A1) U11.11(A0)
TMR_B: J4.73(N48) R34.1(N1)
UNNAMED_1_AD8271_I39_N1: R9.1(N1) U17.7(OUT) U17.8(N1)
UNNAMED_1_AD8271_I39_N2: U16.14(D1) U17.9(N2)
UNNAMED_1_AD8271_I39_P1: U16.15(D2) U17.1(P1)
UNNAMED_1_AD8605_I14_: C26.1(N1) C29.1(N1) D2.2(C) R2.1(N1) R21.1(N1) U7.4(-IN)
UNNAMED_1_AD8605_I14_OUT: U7.1(OUT) U9.15(D2)
UNNAMED_1_AD8605_I35_: U14.1(OUT) U14.4(-IN) U16.1(S2B) U16.12(S1A)
UNNAMED_1_ADG733_I10_D3: C24.1(N1) U9.4(D3)
UNNAMED_1_ADG733_I10_S2A: R6.2(N2) U9.2(S2A) U9.5(S3A) U10.3(S3B) U10.14(D1)
UNNAMED_1_ADG733_I10_S2B: R7.2(N2) U9.1(S2B) U9.3(S3B) U10.5(S3A) U10.15(D2)
UNNAMED_1_CAP_I22_N2: C26.2(N2) R2.2(N2) R7.1(N1) U10.1(S2B)
UNNAMED_1_CAP_I23_N2: C29.2(N2) R6.1(N1) R21.2(N2) U10.12(S1A)
UNNAMED_1_CAP_I31_N2: C24.2(N2) R1.1(N1) U14.3(+IN)
UNNAMED_3_AD8271_I12_N1: R10.1(N1) U12.7(OUT) U12.8(N1)
UNNAMED_3_AD8271_I12_N2: U11.14(D1) U12.9(N2)
UNNAMED_3_AD8271_I12_P1: U11.15(D2) U12.1(P1)
UNNAMED_3_AD8605_I18_: C11.2(N2) R8.1(N1) U3.3(+IN)
UNNAMED_3_AD8605_I18__1: U3.1(OUT) U3.4(-IN) U11.1(S2B) U11.12(S1A)
UNNAMED_3_AD8605_I43_: C53.1(N1) C56.1(N1) D3.2(C) R14.1(N1) R54.1(N1) U5.4(-IN)
UNNAMED_3_AD8605_I43_OUT: U1.15(D2) U5.1(OUT)
UNNAMED_3_ADG733_I33_D1: R27.2(N2) U1.2(S2A) U1.5(S3A) U2.3(S3B) U2.14(D1)
UNNAMED_3_ADG733_I33_D2: R11.2(N2) U1.1(S2B) U1.3(S3B) U2.5(S3A) U2.15(D2)
UNNAMED_3_ADG733_I33_S1A: C56.2(N2) R27.1(N1) R54.2(N2) U2.12(S1A)
UNNAMED_3_ADG733_I33_S2B: C53.2(N2) R11.1(N1) R14.2(N2) U2.1(S2B)
UNNAMED_3_ADG733_I37_D3: C11.1(N1) U1.4(D3)
UNNAMED_5_7408_I44_B: R29.2(N2) U15.2(B)
UNNAMED_5_7408_I44_OUT: R41.1(N1) U15.3(OUT)
UNNAMED_5_7408_I45_A: R35.2(N2) U15.4(A)
UNNAMED_5_7408_I45_OUT: R42.1(N1) U15.6(OUT)
UNNAMED_5_7408_I46_A: R37.2(N2) U15.9(A)
UNNAMED_5_7408_I46_OUT: R43.1(N1) U15.8(OUT)
UNNAMED_5_AD779X_I58_AIN3NEGP2: R16.1(N1) U13.4(AIN3_NEG_P2)
UNNAMED_5_AD779X_I58_AIN3POSP1: R17.1(N1) U13.3(AIN3_POS_P1)
UNNAMED_5_AD8605_I7_: R15.2(N2) R28.1(N1) U19.1(OUT) U19.4(-IN)
UNNAMED_5_AD8605_I7__1: C45.1(N1) R4.1(N1) R15.1(N1) U18.6(VOUT) U19.3(+IN)
UNNAMED_5_CN120PV2_I25_N56: J4.56(N56) R32.1(N1) U8.1(A0)
UNNAMED_5_CN120PV2_I26_N37: J4.84(N37) R23.1(N1)
UNNAMED_5_CN120PV2_I26_N39: J4.82(N39) R22.1(N1)
UNNAMED_5_CN120PV2_I26_N41: J4.80(N41) U8.5(SDA)
UNNAMED_5_CN120PV2_I26_N42: J4.79(N42) U8.6(SCL)
UNNAMED_5_IC24FC256_I31_A1: R31.2(N2) R46.1(N1) U8.2(A1)
UNNAMED_5_RES_I40_N2: R34.2(N2) R36.2(N2) R39.1(N1) R40.1(N1)
UNNAMED_6_AD713N_I22_INV: C14.1(N1) R13.1(N1) U6.2(INV)
UNNAMED_6_AD713N_I22_NINV: U4.14(D1) U6.3(NINV)
UNNAMED_6_AD713N_I22_OUT: C14.2(N2) R3.1(N1) U6.1(OUT)
UNNAMED_6_AD713N_I29_INV: C58.1(N1) R30.1(N1) U6.9(INV)
UNNAMED_6_AD713N_I29_NINV: U4.15(D2) U6.10(NINV)
UNNAMED_6_AD713N_I29_OUT: C58.2(N2) R26.1(N1) U6.8(OUT)
UNNAMED_6_AD713N_I36_INV: C48.1(N1) R24.1(N1) U6.6(INV)
UNNAMED_6_AD713N_I36_NINV: U4.4(D3) U6.5(NINV)
UNNAMED_6_AD713N_I36_OUT: C48.2(N2) R19.1(N1) U6.7(OUT)
UNNAMED_6_AD713N_I54_INV: U6.13(INV) U6.14(OUT)
UNNAMED_6_ADP7104_I1_EN: R48.1(N1) R49.1(N1) U20.5(EN)
UNNAMED_6_ADP7104_I1_SENSE: R50.1(N1) R51.1(N1) R52.2(N2) U20.2(SENSE)
UNNAMED_6_ADP7104_I1_VIN: C51.P(N1) C52.1(N1) Q4.2(S) R48.2(N2) U20.8(VIN)
UNNAMED_6_CAP_I16_N2: C55.2(N2) R51.2(N2)
UNNAMED_6_CN2P_I11_N1: J2.1(N1) R44.1(N1)
UNNAMED_6_RES_I8_N1: Q4.1(G) R38.1(N1)
UNNAMED_6_RES_I10_N2: Q4.3(D) R44.2(N2)
UNNAMED_6_RES_I21_N2: Q1.1(B) R3.2(N2)
UNNAMED_6_RES_I24_N2: Q1.2(E) R12.1(N1) R13.2(N2)
UNNAMED_6_RES_I30_N2: Q3.2(E) R25.1(N1) R30.2(N2)
UNNAMED_6_RES_I33_N2: Q3.1(B) R26.2(N2)
UNNAMED_6_RES_I37_N2: Q2.2(E) R18.1(N1) R24.2(N2)
UNNAMED_6_RES_I40_N2: Q2.1(B) R19.2(N2)
V_DEMODULATED_0: C2.1(N1) C42.1(N1) R9.2(N2) U13.5(AIN1_POS)
V_DEMODULATED_1: C44.1(N1) C46.1(N1) R10.2(N2) U13.7(AIN2_POS)
VREF: C1.1(N1) C2.2(N2) C6.1(N1) C7.1(N1) C8.1(N1) C9.1(N1) C10.1(N1) C33.1(N1) C34.1(N1) C35.1(N1) C36.1(N1) C46.2(N2) D2.1(A) D3.1(A) R1.2(N2) R8.2(N2) R28.2(N2) U2.2(S2A) U2.4(D3) U2.13(S1B) U5.3(+IN) U7.3(+IN) U10.2(S2A) U10.4(D3) U10.13(S1B) U11.2(S2A) U11.13(S1B) U12.2(P2) U13.6(AIN1_NEG) U13.8(AIN2_NEG) U13.9(REFIN_POS) U16.2(S2A) U16.13(S1B) U17.2(P2)

Pads without a net: J4 1 2 5 7 8 9 10 12 13 14 15 16 18 19 20 21 22 24 25 26 27 29 30 31 32 33 34 35 37 38 39 41 42 45 47 49 50 51 53 54 55 57 59 60 61 62 64 65 66 67 68 70 71 72 74 87 88 89 90 91 92 94 95 96 97 99 100 101 102 103 105 106 107 108 110 111 112 113 114 119 120; U12 3 4 10; U13 11; U15 11; U17 3 4 10; U18 1 3 5 7 8; U20 4 7

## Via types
v1: diameter 0.635, hole 0.305, TOP to BOTTOM, 202 vias
v2: diameter 0.635, hole 0.33, TOP to BOTTOM, 9 vias

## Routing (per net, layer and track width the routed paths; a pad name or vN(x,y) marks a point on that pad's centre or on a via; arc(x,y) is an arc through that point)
0.83VREF: length 85.2
  TOP w0.381: 21.74,28.28 22.29,28.28 22.88,27.69 24.14,27.69 24.2,27.63 U4.13 ; 21.74,28.28 v1(21.74,29.59) 21.73,29.58 U4.1 ; 21.74,28.28 U4.3
  TOP w0.508: R4.2 R5.1 R20.1 C5.1 75.08,12.95 71.78,12.95 70.26,14.48 62.89,14.48 62.38,14.99 v1(62.38,17.27)
  BOTTOM w0.508: v1(62.38,17.27) 62.88,17.77 62.88,20.21 62.38,20.7 49.43,20.7 38.89,31.24 36.86,31.24 34.95,29.34 29.36,29.34 28.73,29.97 22.12,29.97 v1(21.74,29.59)
+3.3V: length 49.9
  TOP w0.305: v1(43.85,10.28) J4.116
  TOP w0.508: C47.1 39.27,18.12 39.27,16.34 ; 39.27,16.34 39.39,16.22 U8.8 v1(41.43,16.22) 41.51,16.22 48.29,22.99 56.16,22.99 56.54,23.37 56.54,23.91 C28.1 58.89,24.13 59.73,24.97 59.73,25.39 60.03,25.69 U13.14 61.01,25.67 62,25.67 62.01,25.65 v1(62.51,25.65) ; 39.27,16.34 38.21,16.34 36.91,15.04 36.47,15.04 36.34,14.91 U8.3 34.19,14.91 33.66,14.39 R31.1 ; R33.2 62.13,22.23 v1(61.87,22.48)
  BOTTOM w0.508: v1(43.85,10.28) 43.85,13.83 41.47,16.22 v1(41.43,16.22) ; v1(62.51,25.65) 61.87,25.02 v1(61.87,22.48)
AGND: length 239.1
  TOP w0.203: U12.5 v1(99.1,34.02) ; U17.5 v1(69.89,63.23)
  TOP w0.305: C40.2 67.75,60.58 69.37,60.58 69.89,61.1 U17.5 ; U12.5 99.1,32.02 98.45,31.37 96.96,31.37 C37.2
  TOP w0.381: J4.4 44.45,4.42 v1(44.73,4.7) 45.05,4.38 J4.3 ; J4.117 44.45,7.39 v1(44.73,7.11) 45.05,7.43 J4.118 ; J4.23 v1(33.05,4.57) ; J4.52 v1(15.65,4.57) ; J4.40 v1(22.85,4.54) ; J4.104 v1(36.65,7.29) ; J4.93 v1(30.05,7.29) ; J4.36 v1(25.25,4.57) ; J4.11 v1(40.25,4.61) ; U8.7 v1(38.76,15.57) ; J4.63 v1(12.05,7.37) ; J4.86 v1(25.85,7.28) ; J4.46 v1(19.25,4.52) ; J4.81 v1(22.85,7.33) ; J4.69 v1(15.65,7.37) ; J4.75 v1(19.25,7.37) ; U13.10 59.65,28.3 C1.2 ; J4.115 v1(43.25,7.16) ; J4.109 v1(39.65,7.24) ; J4.58 v1(12.05,4.53) ; J4.17 v1(36.65,4.52) ; J4.28 v1(30.05,4.52) ; J4.98 v1(33.05,7.24) ; U8.4 v1(36.98,14.26) ; J4.6 v1(43.25,4.66)
  TOP w0.508: C34.2 85.88,24.13 v1(84.86,23.11) ; C22.2 v1(65.56,13.34) ; U16.7 v1(61.65,64.36) ; v1(61.65,64.36) 62.07,64.36 62.3,64.14 U16.6 ; v1(61.65,64.36) 61.24,64.36 61,64.12 U16.8 ; 54.66,67.41 54.75,67.32 U10.8 ; 54.66,67.41 54.98,67.73 C10.2 ; 54.66,67.41 v1(54.1,67.41) ; C52.2 v1(9.55,64.14) ; C28.2 v1(53.87,24.13) ; U4.5 20.8,26.98 v1(21.11,26.67) 20.77,26.33 U4.6 ; C44.2 v1(91.97,24.13) ; R25.2 v1(20.22,19.69) ; U11.4 v1(92.81,35.25) ; v1(92.81,35.25) 93.24,35.25 93.46,35.04 U11.3 ; v1(92.81,35.25) 92.35,35.25 92.16,35.05 U11.5 ; U7.2 v1(41.68,73.03) 40.83,72.17 C8.2 ; 33.43,28.58 v1(33.43,30.35) ; v1(83.31,38.2) 82.89,38.2 82.66,37.97 U2.6 ; v1(83.31,38.2) 83.72,38.2 ; v1(83.31,38.2) U2.7 ; U11.8 90.21,34.92 90.43,35.15 v1(90.86,35.15) ; U1.8 83.96,28.99 83.72,29.24 v1(83.31,29.24) ; U16.5 62.95,64.26 63.14,64.46 v1(63.6,64.46) ; v1(56.67,57.15) 56.92,57.15 57.56,57.78 U14.2 ; U1.13 v1(81.36,31.68) ; v1(81.36,31.68) 81.81,31.68 82.01,31.88 U1.12 ; v1(81.36,31.68) 80.91,31.68 80.71,31.88 U1.14 ; U4.7 20.83,25.68 v1(21.11,25.4) 20.74,25.03 U4.8 ; U16.4 v1(63.6,64.46) ; v1(63.6,64.46) 64.03,64.46 64.25,64.25 U16.3 ; U9.14 51.5,61.09 51.7,60.89 v1(52.15,60.89) ; v1(38.51,19.43) 37.49,18.41 R32.2 ; C57.2 v1(10.19,24.77) ; v1(68.35,16.26) 66.57,16.26 C25.2 ; U11.9 v1(90.21,29.2) ; R49.2 v1(21.62,72.9) ; C5.2 v1(72.42,14.61) ; U6.12 U6.11 v1(13.87,18.03) ; v1(90.86,35.15) 91.36,35.15 91.51,35.01 U11.6 ; v1(90.86,35.15) U11.7 ; U3.2 86.77,28.58 86.13,27.94 v1(85.88,27.94) ; U19.2 v1(65.18,10.16) ; C12.2 v1(14.63,33.66) ; v1(54.1,67.41) U10.7 ; v1(54.1,67.41) 53.62,67.41 53.45,67.24 U10.6 ; C13.2 v1(20.47,31.75) ; C33.2 70.04,42.96 v1(70.89,43.81) U5.2 ; C38.2 v1(59.59,63.5) ; C36.2 84.04,38.52 83.72,38.2 ; U9.7 v1(54.1,58.45) ; v1(54.1,58.45) 53.62,58.45 53.45,58.28 U9.6 ; v1(54.1,58.45) 54.51,58.45 54.75,58.2 U9.8 ; U9.12 52.8,61.09 52.6,60.89 v1(52.15,60.89) ; U1.7 v1(83.31,29.24) ; v1(83.31,29.24) 82.83,29.24 82.66,29.07 U1.6 ; C4.2 v1(63.91,15.75) ; C42.2 v1(62.76,53.34) ; C45.2 v1(78,8.89) ; C39.2 v1(98.83,23.11) ; U13.10 v1(62.66,28.3) ; C51.N v1(6.76,49.91) ; 83.72,38.2 83.96,37.96 U2.8 ; U4.2 v1(18.21,28.93) ; U4.12 v1(23.85,26.98) ; C21.2 v1(13.49,26.8) ; R16.2 v1(72.42,26.04) ; 83.96,42.29 v1(83.96,40.52) ; C7.2 v1(46.8,67.53) ; C35.2 v1(76.01,38.32) ; v1(62.51,27.18) 62.33,27 U13.12 59.33,27 58.94,27.39 C43.2 ; C54.2 v1(28.35,65.41) ; R46.2 v1(30.51,18.41) ; U18.4 v1(87.4,8.89) 88.46,7.84 C20.2 89.22,8.38 C23.2 ; C6.2 v1(70,6.35) ; R50.2 v1(19.58,59.05) ; C47.2 v1(42.57,18.41) ; C31.2 v1(48.03,57.53) ; U10.9 v1(54.75,69.73) ; C41.2 v1(69.62,52.32) ; R5.2 v1(82.07,11.43) ; C30.2 v1(46.67,69.63) ; v2(18.19,68.58) 17.55,69.22 U20.6 ; C32.2 v1(88.8,34.29) ; v1(52.15,60.89) U9.13 ; R20.2 v1(81.81,14.61) ; R18.2 v1(3.84,20.83) ; C3.2 v1(58.83,15.75) ; U15.7 v1(39.78,25.4) ; R38.2 v1(8.24,69.3) ; v1(55.65,52.32) 56.67,53.34 C9.2 ; R12.2 v1(7.9,26.92) ; C17.2 v1(75.88,40.42) ; 34.7,28.58 v1(34.7,30.35) ; R17.2 v1(72.54,23.5) ; C18.2 v1(77.24,28.32) ; C27.2 v1(38.51,73.41) ; 20.85,69.22 v1(22.38,69.22) ; C16.2 v1(15.9,25.4) ; U16.9 v1(61,58.28) ; C49.2 v1(35.46,31.75) ; C15.2 v1(67.72,44.2) ; C19.2 v1(7.9,14.86)
  vias: v2(17.3,69.72) v2(17.3,68.58) v2(17.3,67.44) v2(18.19,69.72) v2(18.19,67.44) v2(19.08,69.72) v2(19.08,68.58) v2(19.08,67.44)
AVCC: length 56.4
  TOP w0.203: U17.6 v1(69.89,58.91) ; U12.6 v1(99.1,29.7)
  TOP w0.305: C43.1 59.23,26.34 U13.13 63.07,26.34 v1(63.78,27.05) ; U12.6 99.1,26.52 C39.1 ; U17.6 69.89,55.73 C41.1
  TOP w0.508: L1.1 v1(62.1,19.53) ; U16.16 v1(65.55,58.41) ; C25.1 v1(66.45,20.7) ; U5.5 69.34,47.53 v1(68.86,48.01) 68.48,48.01 67.72,47.24 C15.1 ; C38.1 56.71,62.39 v1(56.61,62.29) U14.5 ; C20.1 v1(88.67,4.83) ; C31.1 49.77,60.54 v1(50.2,60.97) U9.16 ; C17.1 v1(77.24,43.43) ; C18.1 78.98,31.33 v1(79.41,31.76) U1.16 ; C22.1 68.57,11.43 U19.5 v1(70.32,11.11) ; U18.2 v1(87.27,6.35) ; C40.1 v1(67.72,57.66) ; U11.16 v1(94.76,29.2) ; C37.1 v1(96.93,28.45) ; U3.5 v1(85.82,33.08) 85.92,33.18 C32.1 ; 79.41,42.29 v1(79.41,40.52) ; C30.1 v1(48.03,72.64) ; C27.1 38.51,76.45 39.4,77.34 v1(39.65,77.34) 40.26,76.74 U7.5 ; C4.1 v1(63.91,20.19) ; C23.1 v1(91.85,3.94) ; U10.16 v1(50.2,69.73)
DVCC: length 15
  TOP w0.508: C55.1 v1(20.73,65.79) ; 32.16,28.58 v1(32.16,30.35) 32.16,31.33 C49.1 ; C3.1 58.83,18.8 59.59,19.56 v1(60.21,19.56) 60.63,19.14 L1.2 ; C54.1 v1(22.38,65.41) ; v1(10.21,30.58) L2.2 10.19,29.57 C57.1 ; 20.85,66.67 v1(22.25,66.67) ; R52.1 v1(18.4,65.49)
CHAN0_GO/G1: length 107.2
  TOP w0.203: v1(54.13,59.82) v1(54.13,60.96) 54.13,62.59 U9.10 ; U9.10 U9.11 ; U9.10 U9.9 ; v1(60.86,21.59) 60.22,21.59 54.76,16.13 54.76,13.08 47.07,5.39 21.8,5.39 21.05,4.64 J4.43 ; U10.11 U10.10 54.1,69.95 v1(53.75,69.6)
  BOTTOM w0.203: v1(54.13,59.82) 54.89,59.05 54.89,39.24 60.86,33.27 v1(60.86,21.59) ; v1(53.75,69.6) 53.24,69.09 53.24,66.55 54.13,65.66 v1(54.13,60.96)
CHAN1_GO/G1: length 93.3
  TOP w0.203: U1.10 83.34,33.38 v1(83.34,31.75) ; U1.10 U1.9 ; U1.10 U1.11 ; 82.66,42.29 83.31,42.29 83.31,40.74 v1(82.96,40.39) ; v1(75.97,23.75) 73.55,21.32 62.01,21.32 61.1,22.24 60.24,22.24 53.49,15.49 53.49,12.95 46.38,5.84 21.36,5.84 20.45,4.93 J4.44
  BOTTOM w0.203: v1(82.96,40.39) 82.45,39.88 82.45,37.34 83.34,36.45 v1(83.34,31.75) 83.34,31.12 v1(75.97,23.75)
LED_BLUE: length 10
  TOP w0.381: Q1.3 6.88,36.39 J1.3
LED_BLUE_ON: length 34.8
  TOP w0.203: v1(20.98,10.67) 20.45,10.14 J4.77 ; v1(37.24,30.35) 37.24,28.58
  BOTTOM w0.203: v1(37.24,30.35) 37.87,29.72 37.87,24.38 37.11,23.62 30.38,23.62 20.98,14.22 v1(20.98,10.67)
LED_CLK: length 20.8
  TOP w0.203: R37.1 R35.1 R29.1 R36.1 v1(25.3,13.21) ; v1(18.06,4.57) 18.06,3.1 J4.48
  BOTTOM w0.203: v1(18.06,4.57) 19.08,5.59 19.84,5.59 25.3,11.05 v1(25.3,13.21)
LED_CLK_BLUE: length 3.1
  TOP w0.203: U4.11 26.77,26.33 R43.2
LED_CLK_GREEN: length 2.6
  TOP w0.203: R42.2 28.11,25.68 U4.10
LED_CLK_RED: length 3.2
  TOP w0.203: U4.9 26.72,25.03 R41.2
LED_GREEN: length 22.6
  TOP w0.381: Q3.3 19.2,23.37 17.3,25.27 17.3,34.48 J1.2
LED_GREEN_ON: length 29.4
  TOP w0.203: J4.76 v1(19.85,10.66) ; v1(37.24,25.27) U15.5
  BOTTOM w0.203: v1(37.24,25.27) 30.51,25.27 19.85,14.62 v1(19.85,10.66)
LED_RED: length 22.9
  TOP w0.381: J1.1 2.69,37.27 Q2.3
LED_RED_ON: length 23.2
  TOP w0.203: U15.1 32.16,22.73 31.9,22.48 v1(30.76,22.48) ; v1(20.6,7.37) 21.05,7.82 J4.78
  BOTTOM w0.203: v1(30.76,22.48) 22,13.72 22,8.76 v1(20.6,7.37)
LED_VCC: length 56.3
  TOP w0.508: L2.1 13.27,29.59 C21.1 13.58,29.72 C16.1 v1(15.9,31.37) ; C19.1 8.06,18.03 U6.4 12.34,18.03 13.61,19.3 13.61,21.72 11.84,23.5 10.06,23.5 8.93,24.63 8.93,26.47 8.92,26.48 8.92,32.51 C12.1 10.06,36.64 J1.4 ; U4.16 25.55,30.99 v1(24.79,31.75) C13.1
  BOTTOM w0.508: v1(24.79,31.75) 23.9,30.86 16.41,30.86 v1(15.9,31.37) 15.9,33.78 12.85,36.83 J1.4
SPI_CLK: length 25
  TOP w0.203: R22.2 51.62,15.46 60.08,23.91 62.67,23.91 63.14,24.38 66.82,24.38 U13.1
SPI_MISO: length 51.1
  TOP w0.203: v1(63.78,25.15) 63.53,24.89 62.26,24.89 62.1,25.04 U13.15 ; v1(63.78,23.75) 63.54,23.51 60.25,23.51 51.55,14.81 51.54,14.81 47.78,11.05 24.92,11.05 24.05,10.18 J4.83
  BOTTOM w0.203: v1(63.78,23.75) v1(63.78,25.15)
SPI_MOSI: length 21.7
  TOP w0.203: R23.2 43.04,15.46 44.73,17.14 52.73,17.14 59.98,24.4 60.98,24.4 U13.16
SPI_SEL_A: length 56.7
  TOP w0.203: U13.2 67.69,25.04 67.97,24.77 67.97,23.11 67.08,22.23 R33.1 63.88,23.1 60.46,23.1 52.22,14.86 52.22,12.95 45.62,6.35 25.55,6.35 25.23,6.68 25.23,7.54 25.25,7.56 J4.85
SYNCH_CLK_0: length 67.7
  TOP w0.203: U16.11 U16.10 61.65,52.48 55.27,46.1 55.27,27.81 54.64,27.18 48.41,27.18 42.06,20.83 24.41,20.83 23.27,19.69 R39.2
SYNCH_CLK_1: length 85.1
  TOP w0.203: U11.11 U11.10 90.83,27.53 90.83,24.26 88.95,22.38 78.99,22.38 75.34,26.04 75.34,30.1 72.42,33.02 57.18,33.02 55.91,31.75 55.91,27.43 54.89,26.42 49.43,26.42 43.33,20.32 25.97,20.32 R40.2
TMR_B: length 9.5
  TOP w0.203: J4.73 18.05,11.17 18.44,11.56 21.49,11.56 23.27,13.34 R34.1
UNNAMED_1_AD8271_I39_N1: length 3.1
  TOP w0.203: R9.1 72.07,55.46 70.89,56.64 U17.8 U17.7
UNNAMED_1_AD8271_I39_N2: length 13.3
  TOP w0.203: U17.9 71.4,57.53 71.4,59.05 70.89,59.56 69.49,59.56 69,59.07 69,57.09 67.02,55.12 64.67,55.12 64.25,55.54 U16.14
UNNAMED_1_AD8271_I39_P1: length 12.7
  TOP w0.203: U16.15 64.9,55.78 65.15,55.52 66.85,55.52 68.59,57.26 68.59,59.24 69.33,59.97 71.43,59.97 71.89,60.44 U17.1
UNNAMED_1_AD8605_I14_: length 28.6
  TOP w0.203: C29.1 R2.1 C26.1 43.81,78.42 42.63,77.24 42.44,77.43 42.44,77.98 41.3,79.12 36.98,79.12 32.79,74.93 32.79,73.03
  TOP w0.305: 42.63,77.24 U7.4
UNNAMED_1_AD8605_I14_OUT: length 22.1
  TOP w0.203: U7.1 40.73,73.72 39.03,72.01 39.03,67.17 42.48,63.72 50.48,63.72 50.85,63.35 U9.15
UNNAMED_1_AD8605_I35_: length 17.2
  TOP w0.203: U16.12 62.95,60.14 v1(62.38,60.71) 58.66,60.71 U14.4 58.51,60.39 57.94,59.82 57.43,59.82 56.61,58.99 U14.1 ; v1(65.94,60.71) 65.55,61.1 U16.1
  BOTTOM w0.203: v1(65.94,60.71) v1(62.38,60.71)
UNNAMED_1_ADG733_I10_D3: length 3
  TOP w0.203: U9.4 52.15,54.41 C24.1
UNNAMED_1_ADG733_I10_S2A: length 24.3
  TOP w0.203: 51.5,67.31 U10.3 ; 51.5,67.31 v1(51.33,67.31) ; 51.5,67.31 U10.14 51.5,74.17 R6.2 ; U9.2 50.85,58.06 v1(51.21,58.42) 52.35,58.42 52.8,57.97 U9.5
  BOTTOM w0.203: v1(51.33,67.31) 53.35,65.29 53.35,60.57 v1(51.21,58.42)
UNNAMED_1_ADG733_I10_S2B: length 25.6
  TOP w0.203: U9.3 51.46,56.73 51.46,55.63 51.33,55.5 50.44,55.5 50.2,55.74 U9.1 v1(50.2,58.41) ; R7.2 50.85,72.96 U10.15 50.85,70.74 50.82,70.71 50.82,69.34 v1(50.19,68.71) ; v1(52.73,64.14) 52.8,64.21 U10.5
  BOTTOM w0.203: v1(50.19,68.71) 50.19,66.67 v1(52.73,64.14) 51.33,62.74 51.33,59.68 50.2,58.55 v1(50.2,58.41)
UNNAMED_1_CAP_I22_N2: length 14.5
  TOP w0.203: C26.2 R2.2 47.82,76.3 R7.1 49.17,72.94 49.17,68.71 50.2,67.68 U10.1
UNNAMED_1_CAP_I23_N2: length 7.9
  TOP w0.203: C29.2 R21.2 53.33,76.3 R6.1 52.8,73.77 U10.12
UNNAMED_1_CAP_I31_N2: length 6.6
  TOP w0.203: C24.2 56.41,55.88 R1.1 56.71,55.92 57.81,57.02 58.19,57.02 58.51,57.34 U14.3
UNNAMED_3_AD8271_I12_N1: length 3.1
  TOP w0.203: R10.1 101.28,26.25 100.1,27.43 U12.8 U12.7
UNNAMED_3_AD8271_I12_N2: length 13.3
  TOP w0.203: U11.14 93.46,26.33 93.88,25.91 96.23,25.91 98.21,27.88 98.21,29.86 98.7,30.35 100.1,30.35 100.61,29.84 100.61,28.32 U12.9
UNNAMED_3_AD8271_I12_P1: length 12.7
  TOP w0.203: U12.1 101.1,31.23 100.64,30.76 98.54,30.76 97.8,30.03 97.8,28.05 96.06,26.31 94.36,26.31 94.11,26.57 U11.15
UNNAMED_3_AD8605_I18_: length 6.6
  TOP w0.203: C11.2 85.62,26.67 R8.1 85.92,26.71 87.02,27.81 87.4,27.81 87.72,28.13 U3.3
UNNAMED_3_AD8605_I18__1: length 17.2
  TOP w0.203: v1(95.15,31.5) 94.76,31.89 U11.1 ; U11.12 92.16,30.93 v1(91.59,31.5) 87.87,31.5 U3.4 87.72,31.18 87.15,30.61 86.64,30.61 85.82,29.78 U3.1
  BOTTOM w0.203: v1(95.15,31.5) v1(91.59,31.5)
UNNAMED_3_AD8605_I43_: length 28.3
  TOP w0.203: D3.2 62,45.72 65.81,49.53 70.89,49.53 71.65,48.77 71.65,48.22 71.84,48.03 73.02,49.21 C53.1 R14.1 R54.1 C56.1
  TOP w0.305: U5.4 71.84,48.03
UNNAMED_3_AD8605_I43_OUT: length 22.1
  TOP w0.203: U5.1 69.94,44.64 68.24,42.94 68.24,37.96 71.69,34.51 79.69,34.51 80.06,34.14 U1.15
UNNAMED_3_ADG733_I33_D1: length 24.3
  TOP w0.203: 80.71,38.1 U2.3 ; 80.71,38.1 80.71,44.96 R27.2 ; 80.71,38.1 v1(80.54,38.1) ; U1.2 80.06,28.85 v1(80.42,29.21) 81.56,29.21 82.01,28.76 U1.5
  BOTTOM w0.203: v1(80.42,29.21) 82.56,31.36 82.56,36.08 v1(80.54,38.1)
UNNAMED_3_ADG733_I33_D2: length 25.6
  TOP w0.203: v1(79.4,39.5) 80.03,40.13 80.03,41.5 80.06,41.53 80.06,43.75 R11.2 ; v1(81.94,34.92) 82.01,35 U2.5 ; U1.3 80.67,27.52 80.67,26.42 80.54,26.29 79.65,26.29 79.41,26.53 U1.1 v1(79.41,29.2)
  BOTTOM w0.203: v1(79.41,29.2) 79.41,29.22 80.54,30.35 80.54,33.53 v1(81.94,34.92) 79.4,37.47 v1(79.4,39.5)
UNNAMED_3_ADG733_I33_S1A: length 7.9
  TOP w0.203: 82.01,42.29 82.01,44.56 R27.1 82.54,47.09 R54.2 C56.2
UNNAMED_3_ADG733_I33_S2B: length 14.5
  TOP w0.203: C53.2 R14.2 77.03,47.09 R11.1 78.38,43.73 78.38,39.5 79.41,38.47 U2.1
UNNAMED_3_ADG733_I37_D3: length 3
  TOP w0.203: U1.4 81.36,25.2 C11.1
UNNAMED_5_7408_I44_B: length 11
  TOP w0.203: R29.2 v1(27.33,17.4) ; U15.2 v1(33.43,21.72)
  BOTTOM w0.203: v1(27.33,17.4) 31.65,21.72 v1(33.43,21.72)
UNNAMED_5_7408_I44_OUT: length 7.1
  TOP w0.203: U15.3 34.7,25.02 34.51,25.21 31.46,25.21 29.87,23.62 R41.1
UNNAMED_5_7408_I45_A: length 12.1
  TOP w0.203: R35.2 v1(29.36,17.4) ; U15.4 v1(35.97,21.72)
  BOTTOM w0.203: v1(29.36,17.4) 29.36,18.54 30.06,19.24 33.49,19.24 v1(35.97,21.72)
UNNAMED_5_7408_I45_OUT: length 10.7
  TOP w0.203: U15.6 38.51,25.15 37.74,25.91 30.09,25.91 R42.1
UNNAMED_5_7408_I46_A: length 21.2
  TOP w0.203: R37.2 31.39,16.89 v1(30.89,17.4) ; 38.51,28.58 v1(38.51,30.35)
  BOTTOM w0.203: v1(30.89,17.4) 33.93,17.4 38.51,21.97 v1(38.51,30.35)
UNNAMED_5_7408_I46_OUT: length 12.2
  TOP w0.203: 39.78,28.58 39.78,27.05 39.27,26.54 31.01,26.54 29.87,27.69 R43.1
UNNAMED_5_AD779X_I58_AIN3NEGP2: length 2.7
  TOP w0.203: R16.1 69.1,26.34 U13.4
UNNAMED_5_AD779X_I58_AIN3POSP1: length 3.8
  TOP w0.203: U13.3 67.8,25.69 68.48,25.02 68.48,24.42 R17.1
UNNAMED_5_AD8605_I7_: length 8.7
  TOP w0.203: R28.1 64.01,11.11 U19.1 67.04,11.11 67.86,10.29 67.86,9.8 68.45,9.21 U19.4 69.49,9.21 69.81,8.89 R15.2
UNNAMED_5_AD8605_I7__1: length 17.9
  TOP w0.203: C45.1 R15.1 72,7.87 68.22,7.87 66.89,9.21 U19.3 ; C45.1 76.39,7.62 U18.6 ; C45.1 R4.1
UNNAMED_5_CN120PV2_I25_N56: length 33.4
  TOP w0.203: v1(36.86,16.26) 35.61,16.26 U8.1 35.57,18.23 R32.1 ; v1(22.25,6.48) 15.39,6.48 13.25,4.33 J4.56
  BOTTOM w0.203: v1(36.86,16.26) 27.08,6.48 v1(22.25,6.48)
UNNAMED_5_CN120PV2_I26_N37: length 22.4
  TOP w0.203: R23.1 42.02,12.83 v1(40.54,12.83) ; v1(40.54,10.41) 25.17,10.41 24.65,9.89 J4.84
  BOTTOM w0.203: v1(40.54,10.41) v1(40.54,12.83)
UNNAMED_5_CN120PV2_I26_N39: length 25
  TOP w0.203: J4.82 23.45,10.34 24.66,11.56 43.29,11.56 R22.1
UNNAMED_5_CN120PV2_I26_N41: length 20.9
  TOP w0.203: U8.5 40.13,14.22 38.89,14.22 36.73,12.07 24.28,12.07 22.25,10.03 J4.80
UNNAMED_5_CN120PV2_I26_N42: length 22.1
  TOP w0.203: U8.6 38.82,14.91 36.47,12.57 23.65,12.57 21.65,10.57 J4.79
UNNAMED_5_IC24FC256_I31_A1: length 4.8
  TOP w0.203: U8.2 33.95,15.57 R31.2 33.43,18.2 R46.1
UNNAMED_5_RES_I40_N2: length 5.7
  TOP w0.203: R39.1 R34.2 R36.2 R40.1
UNNAMED_6_AD713N_I22_INV: length 4.9
  TOP w0.203: C14.1 R13.1 8.5,20.57 U6.2
UNNAMED_6_AD713N_I22_NINV: length 21.7
  TOP w0.203: v1(23.9,28.45) 24.07,28.28 U4.14 ; U6.3 v1(12.47,19.3)
  BOTTOM w0.203: v1(12.47,19.3) 12.47,24.13 16.65,28.31 18.47,28.31 18.61,28.45 v1(23.9,28.45)
UNNAMED_6_AD713N_I22_OUT: length 16.6
  TOP w0.203: U6.1 11.96,21.84 12.22,21.59 12.22,20.19 11.96,19.94 9.3,19.94 9.04,19.69 9.04,19.43 8.53,18.92 5.23,18.92 4.85,19.3 4.85,20.83 5.7,21.68 C14.2 R3.1
UNNAMED_6_AD713N_I29_INV: length 10.4
  TOP w0.203: R30.1 C58.1 18.15,12.7 14.63,12.7 13.74,13.59 13.74,14.99 14.25,15.49 U6.9
UNNAMED_6_AD713N_I29_NINV: length 21.5
  TOP w0.203: v1(13.87,16.76) U6.10 ; U4.15 v1(27.08,28.93)
  BOTTOM w0.203: v1(13.87,16.76) 14.88,16.76 27.05,28.93 v1(27.08,28.93)
UNNAMED_6_AD713N_I29_OUT: length 5
  TOP w0.203: U6.8 17.97,14.22 C58.2 R26.1
UNNAMED_6_AD713N_I36_INV: length 9.4
  TOP w0.203: U6.6 9.68,15.49 8.06,13.88 R24.1 C48.1
UNNAMED_6_AD713N_I36_NINV: length 16.7
  TOP w0.203: U4.4 19.67,27.59 v1(18.16,27.59) ; U6.5 v1(12.47,16.76)
  BOTTOM w0.203: v1(12.47,16.76) 12.47,18.16 18.16,23.85 v1(18.16,27.59)
UNNAMED_6_AD713N_I36_OUT: length 16.2
  TOP w0.203: R19.1 C48.2 1.77,15.58 0.66,14.48 0.66,13.08 1.17,12.57 8.03,12.57 9.68,14.22 U6.7
UNNAMED_6_AD713N_I54_INV: length 1.3
  TOP w0.203: U6.13 U6.14
UNNAMED_6_ADP7104_I1_EN: length 5.8
  TOP w0.508: R48.1 14.16,70.48 15.52,70.48 15.52,71.63 R49.1
UNNAMED_6_ADP7104_I1_SENSE: length 14.7
  TOP w0.508: v1(16.7,65.57) R52.2 R51.1 R50.1 ; v1(22.38,67.94) 20.85,67.94
  BOTTOM w0.508: v1(22.38,67.94) 20.85,67.94 19.2,66.29 17.42,66.29 v1(16.7,65.57)
UNNAMED_6_ADP7104_I1_VIN: length 19.8
  TOP w0.508: C51.P 6.39,60.31 Q4.2 7.57,63.83 9.17,62.23 12.09,62.23 13.87,64.01 C52.1 14,64.26 15.14,64.26 15.52,64.64 U20.8 14.16,66.67 R48.2
UNNAMED_6_CAP_I16_N2: length 2.4
  TOP w0.508: C55.2 20.6,61.59 R51.2
UNNAMED_6_CN2P_I11_N1: length 8.8
  TOP w0.508: R44.1 10.57,74.93 J2.1
UNNAMED_6_RES_I8_N1: length 2.3
  TOP w0.508: R38.1 6.39,67.79 Q4.1
UNNAMED_6_RES_I10_N2: length 3.2
  TOP w0.508: Q4.3 10.57,66.94 R44.2
UNNAMED_6_RES_I21_N2: length 2.6
  TOP w0.203: Q1.1 5.94,25.82 R3.2
UNNAMED_6_RES_I24_N2: length 7.5
  TOP w0.381: R13.2 R12.1 6.88,25.06 6.88,27.41 Q1.2
UNNAMED_6_RES_I30_N2: length 7.4
  TOP w0.381: Q3.2 19.2,20.04 19.2,17.65 20.05,16.8 R25.1 R30.2
UNNAMED_6_RES_I33_N2: length 2.5
  TOP w0.203: R26.2 18.19,20.9 Q3.1
UNNAMED_6_RES_I37_N2: length 7.4
  TOP w0.381: Q2.2 2.82,21.44 2.82,18.96 R18.1 R24.2
UNNAMED_6_RES_I40_N2: length 2.6
  TOP w0.203: Q2.1 1.75,19.7 R19.2
V_DEMODULATED_0: length 36.3
  TOP w0.203: C42.1 67.21,52.83 68.35,51.69 v1(68.61,51.69) 71.15,51.69 72.16,52.7 R9.2 ; C2.1 68.43,27.6 v1(68.43,27.43) 68.43,27.4 68.03,27 U13.5
  BOTTOM w0.203: v1(68.61,51.69) 67.08,50.16 67.08,28.7 68.35,27.43 v1(68.43,27.43)
V_DEMODULATED_1: length 45.1
  TOP w0.203: C46.1 68.35,30.06 v1(68.35,29.84) 68.35,28.83 67.82,28.3 U13.7 ; 96.42,23.62 v1(94.77,21.97) ; 96.42,23.62 97.82,22.23 100.1,22.23 101.37,23.5 R10.2 ; 96.42,23.62 C44.1
  BOTTOM w0.203: v1(68.35,29.84) 68.35,28.7 75.46,21.59 94.39,21.59 v1(94.77,21.97)
VREF: length 362.2
  TOP w0.203: 41.68,76.06 42.63,75.11 ; 44.22,77.47 56.92,77.47 ; 86.13,48.26 73.43,48.26 73.05,47.88 ; U16.2 64.92,62.59 64.92,61.85 ; 71.84,45.9 70.89,46.85 ; 94.13,32.64 94.13,33.38 U11.2
  TOP w0.305: U11.2 94.11,34.65 94.26,34.8 ; 100.6,33.77 U12.2 ; U13.9 62.25,28.95 v1(62.64,29.34) ; 71.39,62.98 U17.2 ; 65.05,64.01 64.9,63.86 U16.2
  TOP w0.381: U13.9 60.23,28.95 59.84,29.34 59.84,29.81 C1.1
  TOP w0.508: C9.1 R1.2 v1(59.72,55.88) ; v1(62.64,29.34) 63.53,29.34 63.91,28.96 63.91,28.95 65.05,28.95 ; 81.36,42.29 81.36,39.37 ; 81.36,39.37 U2.4 81.36,35.5 80.92,35.05 80.42,35.05 80.16,35.31 80.04,35.31 ; 81.36,39.37 84.23,39.37 85.08,40.22 C36.1 90.61,40.22 94.64,36.2 94.64,35.18 ; 64.92,61.85 64.92,60.07 v1(63.91,59.05) 63.6,58.75 U16.13 ; 100.6,33.77 100.6,34.55 99.97,35.18 94.64,35.18 ; 74.32,50.8 64.92,50.8 60.1,45.97 60.1,40.64 D3.1 63.78,40.51 63.78,45.34 67.34,48.9 68.27,48.9 68.28,48.91 68.93,48.91 68.94,48.9 70.64,48.9 70.89,48.64 70.89,46.85 ; 74.32,50.8 86.26,50.8 86.64,50.42 86.64,48.77 86.13,48.26 ; 74.32,50.8 74.19,50.93 74.19,63.12 73.55,63.76 71.39,63.76 ; 42.63,75.11 42.63,74.74 ; 42.63,74.74 U7.3 42.63,71.85 C8.1 42.53,67.48 44.22,65.79 47.99,65.79 C7.1 48.03,64.77 48.49,64.31 50.62,64.31 50.83,64.52 ; 42.63,74.74 43.84,75.95 43.84,77.09 44.22,77.47 ; C2.2 C46.2 70.76,31.46 70.76,31.51 70.02,32.26 68.44,32.26 66.83,30.65 U13.8 65.05,28.95 ; v1(88.93,26.67) R8.2 C34.1 ; 71.84,45.53 73.05,46.74 73.05,47.88 ; 71.84,45.53 U5.3 71.84,42.64 C33.1 71.74,38.27 73.43,36.58 77.2,36.58 C35.1 77.24,35.56 77.7,35.1 79.83,35.1 80.04,35.31 ; 71.84,45.53 71.84,45.9 ; 65.05,28.95 65.05,27.94 65.34,27.65 U13.6 ; 71.39,63.76 71.39,62.98 ; 71.39,63.76 70.76,64.39 65.43,64.39 ; 52.15,68.58 U10.4 52.15,64.71 51.71,64.26 51.21,64.26 50.95,64.52 50.83,64.52 ; 52.15,68.58 U10.13 ; 52.15,68.58 55.02,68.58 55.87,69.43 C10.1 61.28,69.43 65.43,65.28 65.43,64.39 ; 94.13,32.64 94.13,30.86 v1(93.12,29.84) 92.81,29.54 U11.13 ; 80.04,35.31 80.04,36.42 U2.2 ; 41.68,76.06 41.68,77.85 41.3,78.23 38.25,78.23 34.82,74.8 34.82,72.01 34.19,71.37 29.36,71.37 D2.1 34.7,80.01 57.05,80.01 57.43,79.63 57.43,77.98 56.92,77.47 ; 50.83,64.52 50.83,65.63 U10.2 ; 94.64,35.18 94.26,34.8 ; 65.43,64.39 65.05,64.01 ; v1(62.64,9.31) R28.2 63.91,8.13 C6.1
  BOTTOM w0.508: v1(88.93,26.67) 89.94,26.67 v1(93.12,29.84) ; v1(62.64,9.31) 62.67,9.31 64.68,11.32 64.68,20.52 64.67,20.53 64.67,28.45 63.78,29.34 v1(62.64,29.34) 62,29.97 D3.1 ; v1(59.72,55.88) 60.73,55.88 v1(63.91,59.05)

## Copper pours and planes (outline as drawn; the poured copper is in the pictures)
AGND on L2_GND: 1.04,0.63 1.04,80.65 24.54,80.65 24.54,68.58 36.6,68.58 36.6,47.62 51.84,47.62 51.84,27.94 54.38,27.94 54.38,28.58 52.48,28.58 52.48,48.26 37.24,48.26 37.24,69.22 25.17,69.22 25.17,80.65 103.91,80.65 103.91,0.63 61.37,0.63 61.37,20.32 60.73,20.32 60.73,0.63
AVCC on L3_PWR: 25.17,80.65 25.17,69.22 37.24,69.22 37.24,48.26 52.48,48.26 52.48,28.58 61.37,28.58 61.37,0.63 103.91,0.63 103.91,80.65
DVCC on L3_PWR: 1.04,0.63 60.73,0.63 60.73,27.94 51.84,27.94 51.84,47.62 36.6,47.62 36.6,68.58 24.54,68.58 24.54,80.65 1.04,80.65

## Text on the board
Ref Des/Silkscreen Top: VIN 6-12VDC | B1 | A03527 REV B | EVAL_CN0312-SDPZ
PAGE_OUTLINE: B | PER ALP3527B | 05FEB13 | L.O.
DIMENSION: MAX | SEE NOTE 15 | 2X | .042 R 2X
BODY_CENTER: IMMERSION GOLD BOARD PLATING, 2-8 MICRO INCHES GOLD OVER | QQ-N-290, CLASS I. | 15.    FILL VIAS INDICATED WITH NON-CONDUCTIVE EPOXY AND GRIND FLUSH | PRIOR TO OVERPLATING.
User.11: 08-      -07 | LYR2 GND
User.12: LYR3 PWR | 08-      -08
User.16: 25JUN12 | L OROZCO
User.18: FIGURE | SIZE | 12.0 | 13.0 | 30.0 | 45.0 | 50.0 | 28.0 | 43.0 | 105.0 | 122.0 | PLATED | NON-PLATED | FINISHED HOLES IN MILS | ALL UNITS ARE IN MILS | QTY | 202 | 9 | 4 | 2 | 1 | TOLERANCE/NOTES
